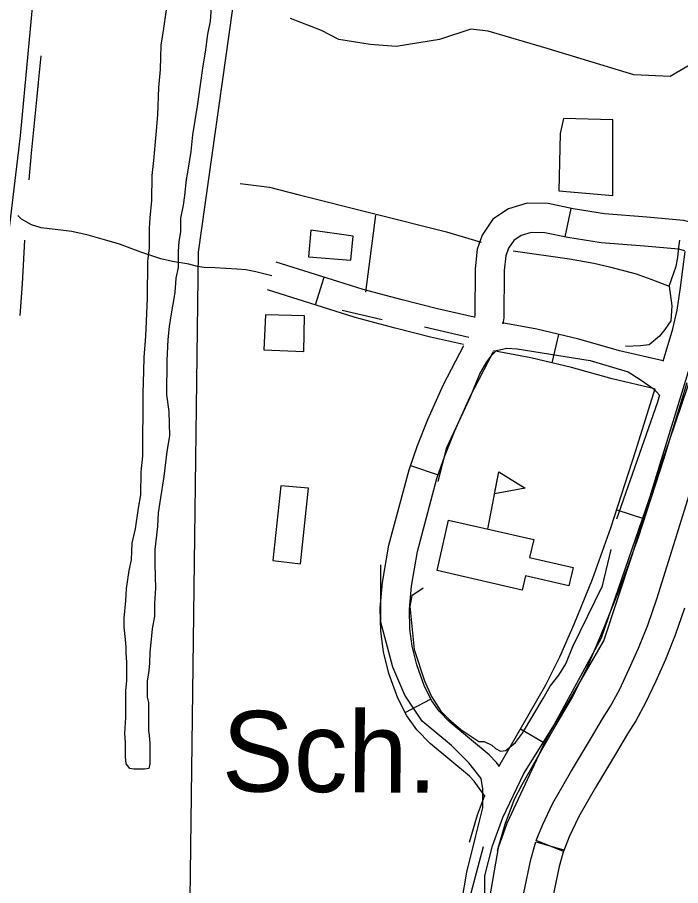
# Model space of a CAD drawing. Extents: x 3172297 to 3210190, y 958463 to 983887.
# Drawn here: x 3187024 to 3187707, y 978578 to 979472 of the extents above; entities that cross this region are included whole.
import ezdxf

# ---------------------------------------------------------------- set-up
doc = ezdxf.new("R2010")
doc.units = 0
for name, color, linetype in [('V-BLDG-IDEN', 7, 'Continuous'), ('V-BLDG-OTLN', 7, 'Continuous'), ('V-LEVE-TOET', 7, 'Continuous'), ('V-ROAD-CNTR', 7, 'Continuous'), ('V-SITE-VEGE', 7, 'Continuous'), ('V-TOPO-SHOR', 7, 'Continuous'), ('V-UTIL-LINE', 7, 'Continuous')]:
    doc.layers.add(name, color=color, linetype=linetype)

msp = doc.modelspace()

# ---------------------------------------------------------------- linework, layer by layer
at = {"layer": 'V-BLDG-OTLN'}
msp.add_line((3187508.514340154, 978944.6913213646), (3187519.741340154, 979003.6313213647), dxfattribs=at)
for points in [[(3187582.968542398, 979351.9644093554), (3187581.7884385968, 979292.9592192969), (3187637.253317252, 979288.2388040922), (3187637.253317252, 979366.1256549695), (3187586.5088538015, 979367.3057587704)], [(3187326.2959656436, 979252.2456381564), (3187323.935758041, 979225.1032507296), (3187367.5995986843, 979221.562939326), (3187369.9598062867, 979246.3451191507)], [(3187279.5343525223, 979165.3604957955), (3187278.059222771, 979129.3673298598), (3187319.067829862, 979127.5971741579), (3187319.9529077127, 979164.1803919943)], [(3187519.741340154, 979003.6313213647), (3187547.0503401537, 978986.6713213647), (3187515.418340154, 978980.9373213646)], [(3187295.6132668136, 978989.0824904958), (3187287.352540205, 978912.3757434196), (3187315.6750314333, 978908.8354320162), (3187323.935758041, 978986.7222828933)], [(3187468.154000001, 978953.8619999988), (3187555.811000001, 978933.8629999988), (3187551.610000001, 978915.4489999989), (3187596.418000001, 978905.2259999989), (3187592.113000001, 978886.3559999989), (3187547.227000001, 978896.5959999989), (3187543.879000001, 978881.9179999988), (3187456.300000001, 978901.8939999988)]]:
    msp.add_lwpolyline(points, close=True, dxfattribs=at)
at = {"layer": 'V-LEVE-TOET'}
msp.add_lwpolyline([(3187505.89, 978537.949), (3187505.563, 978587.59), (3187513.281, 978618.4060000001), (3187524.04, 978647.844), (3187545.619, 978692.898), (3187591.032, 978765.373), (3187628.0640000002, 978829.698), (3187657.186, 978917.922), (3187721.622, 979128.143)], dxfattribs=at)
at = {"layer": 'V-ROAD-CNTR'}
for p, q in [((3187588.0486666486, 979245.4247996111), (3187594.227313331, 979274.781644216)), ((3187331.165577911, 979175.3671415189), (3187340.2089301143, 979203.9716478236)), ((3187574.8979231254, 979115.8377878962), (3187581.820606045, 979145.028136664)), ((3187429.0710944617, 979010.2216276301), (3187457.398413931, 979000.3442306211)), ((3187641.2831362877, 978964.3095301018), (3187669.829274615, 978955.0835891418)), ((3187423.445433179, 978755.9751498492), (3187450.094710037, 978769.7525241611)), ((3187542.022944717, 978738.9541968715), (3187568.0250511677, 978723.9912272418))]:
    msp.add_line(p, q, dxfattribs=at)
for points in [[(3187048.2272379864, 979431.8138659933), (3187044.309334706, 979390.7621408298)], [(3187045.5481547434, 979403.742514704), (3187038.605801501, 979331.5318478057), (3187036.1556204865, 979304.1892211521)], [(3187715.649442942, 979260.9178099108), (3187709.9216832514, 979262.36518663), (3187672.2151692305, 979265.9264897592), (3187628.581476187, 979269.1162086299), (3187596.387500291, 979274.3269961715), (3187570.52576696, 979279.7700373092), (3187549.1461948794, 979280.2356563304), (3187529.86811972, 979274.3719679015), (3187513.674759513, 979263.5723010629), (3187502.814662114, 979247.337353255), (3187497.595053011, 979232.7082982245), (3187495.5340465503, 979212.5232305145), (3187495.2218352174, 979165.2778751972), (3187494.66566424, 979162.5037352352)], [(3187286.228, 979205.306), (3187269.782, 979209.582), (3187259.264, 979211.64), (3187250.169, 979212.291), (3187227.375, 979213.561), (3187216.5100000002, 979214.083), (3187209.774, 979215.103), (3187200.669, 979217.289), (3187183.8850000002, 979220.25), (3187171.9450000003, 979223.0090000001), (3187151.361, 979229.605), (3187129.23, 979237.846), (3187116.219, 979241.779), (3187097.058, 979247.323), (3187080.271, 979251.111), (3187048.8710000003, 979254.912), (3187038.815, 979257.919), (3187028.508, 979263.637), (3187024.8713716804, 979267.3825869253)], [(3187711.4425745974, 979231.0378636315), (3187704.8063167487, 979232.71481337), (3187669.7108307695, 979236.0295102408), (3187625.0845238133, 979239.2917913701), (3187590.8984997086, 979244.8250038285), (3187567.0802330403, 979249.8379626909), (3187553.2878051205, 979250.1383436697), (3187542.8318802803, 979246.9580320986), (3187535.2892404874, 979241.9276989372), (3187529.8193378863, 979233.750646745), (3187527.070946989, 979226.0477017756), (3187525.52395345, 979210.8967694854), (3187525.2021647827, 979162.2021248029), (3187523.9851124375, 979156.1315571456)], [(3187031.6632658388, 979241.9662575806), (3187029.2173945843, 979197.2261635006), (3187026.6885373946, 979164.5274314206)], [(3187689.132357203, 979117.5953481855), (3187698.9637646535, 979150.8205543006), (3187703.6057943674, 979170.1912449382), (3187706.8920058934, 979193.38427755), (3187711.6881049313, 979230.3480557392)], [(3187494.581906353, 979162.8372869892), (3187456.604749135, 979171.5495847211), (3187420.535867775, 979180.7263095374), (3187380.212822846, 979191.3011747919), (3187354.0384344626, 979199.5994326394), (3187290.7496753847, 979219.6082533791)], [(3187483.545753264, 979134.5897739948), (3187449.551250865, 979142.388415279), (3187413.032132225, 979151.6796904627), (3187371.8691771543, 979162.4748252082), (3187344.9835655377, 979170.9985673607), (3187281.7063246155, 979191.003746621)], [(3187689.1730351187, 979117.8010878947), (3187644.207267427, 979128.3184351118), (3187602.296567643, 979140.1721278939), (3187559.083073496, 979150.4204918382), (3187523.485912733, 979156.8806349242)], [(3187505.9504005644, 978669.3924843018), (3187494.3824032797, 978685.0995811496), (3187489.5336155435, 978690.1223627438), (3187449.0906654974, 978723.8788170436), (3187435.3618710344, 978738.0852313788), (3187425.2992005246, 978752.3894478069), (3187415.824975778, 978770.7152356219), (3187406.806918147, 978796.1216936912), (3187401.2819581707, 978818.2547197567), (3187398.258113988, 978839.5767814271), (3187397.7860149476, 978863.2217052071), (3187400.271350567, 978889.785445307), (3187406.7544363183, 978928.04319572), (3187427.4458907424, 979005.5607169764), (3187436.1603434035, 979030.552836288), (3187446.8752577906, 979057.5343441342), (3187462.9317218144, 979093.5245172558), (3187483.7836879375, 979133.7128668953)], [(3187520.28300559, 978700.5208497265), (3187517.3535967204, 978704.4984188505), (3187509.9963844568, 978712.1196372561), (3187469.547334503, 978745.8811829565), (3187458.5561289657, 978757.2547686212), (3187451.010799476, 978767.9805521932), (3187443.4130242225, 978782.6767643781), (3187435.563081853, 978804.7923063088), (3187430.7660418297, 978824.0092802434), (3187428.215886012, 978841.9912185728), (3187427.8139850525, 978862.1202947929), (3187430.0366494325, 978885.876554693), (3187436.0995636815, 978921.65480428), (3187456.1421092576, 978996.7412830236), (3187464.2776565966, 979020.073163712), (3187474.5267422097, 979045.8816558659), (3187489.968278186, 979080.4934827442), (3187514.4072915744, 979127.595209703)], [(3187680.215870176, 979089.0864509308), (3187636.704732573, 979099.2635648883), (3187594.749432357, 979111.1298721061), (3187552.938926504, 979121.0455081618), (3187514.3678498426, 979128.0453550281)], [(3187518.3680177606, 978613.7416318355), (3187526.4887806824, 978641.009604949), (3187535.885474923, 978666.6561358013), (3187543.768977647, 978681.8399015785), (3187575.6341894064, 978737.2141119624), (3187594.5580746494, 978769.919840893), (3187610.007775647, 978800.3921095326), (3187624.97358606, 978835.220837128), (3187644.2109237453, 978882.4796389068), (3187663.7333959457, 978936.2222289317), (3187689.6704516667, 979016.4745071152), (3187713.9221614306, 979095.6421023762)], [(3187519.8261649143, 978700.3814372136), (3187549.6498105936, 978752.2078880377), (3187568.1759253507, 978784.2261591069), (3187582.820224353, 978813.1098904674), (3187597.29641394, 978846.7991628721), (3187616.209076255, 978893.2603610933), (3187635.3526040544, 978945.9597710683), (3187661.0535483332, 979025.4814928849), (3187680.655575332, 979089.4706035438)], [(3187711.006384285, 978863.2704616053), (3187701.2809149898, 978835.4203467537), (3187691.33240909, 978810.3231891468), (3187681.41010689, 978788.2167485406), (3187670.808130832, 978765.6971480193), (3187660.80950818, 978747.3592220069), (3187652.4440869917, 978733.7540893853), (3187641.172948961, 978714.7984920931), (3187619.5280336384, 978678.718977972), (3187602.2314273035, 978648.6971931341), (3187592.3291294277, 978627.8160320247), (3187586.3319659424, 978612.8556901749), (3187558.4860340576, 978624.0183098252), (3187564.8268705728, 978639.8359679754), (3187575.6385726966, 978662.634806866), (3187593.6659663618, 978693.925022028), (3187615.4170510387, 978730.1815079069), (3187626.7719130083, 978749.2779106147), (3187634.8444918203, 978762.4067779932), (3187644.0438691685, 978779.2788519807), (3187654.1518931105, 978800.7492514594), (3187663.68959091, 978821.9988108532), (3187673.1630850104, 978845.8976532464), (3187682.517615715, 978872.6855383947), (3187701.782294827, 978934.4378940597), (3187737.5169503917, 979049.2252090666)], [(3187489.6159822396, 978622.3043681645), (3187498.0012193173, 978650.460395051), (3187505.0648461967, 978669.7392520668)], [(3187545.587983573, 978570.1138332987), (3187552.793886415, 978604.4055087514), (3187557.9873754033, 978622.5621356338), (3187586.8306245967, 978614.3118643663), (3187581.932113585, 978597.1864912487), (3187575.380016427, 978566.0061667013)], [(3187555.3000000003, 978083.843), (3187542.461, 978124.291), (3187538.0500000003, 978142.23), (3187530.483, 978180.337), (3187523.896, 978214.319), (3187518.606, 978244.9720000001), (3187511.526, 978305.343), (3187500.203, 978406.549), (3187491.577, 978484.559), (3187488.642, 978519.519), (3187488.818, 978540.666), (3187491.327, 978570.098), (3187503.992, 978618.023)]]:
    msp.add_lwpolyline(points, dxfattribs=at)
at = {"layer": 'V-SITE-VEGE'}
for p, q in [((3187174.878, 979460.081), (3187178.958, 979486.601)), ((3187224.235, 979486.302), (3187222.554, 979467.5750000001)), ((3187222.554, 979467.5750000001), (3187220.123, 979454.318)), ((3187172.423, 979442.9230000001), (3187174.878, 979460.081)), ((3187220.123, 979454.318), (3187217.657, 979435.5969999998)), ((3187171.4760000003, 979417.9450000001), (3187172.423, 979442.9230000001)), ((3187217.657, 979435.5969999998), (3187215.222, 979421.5580000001)), ((3187215.222, 979421.5580000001), (3187209.483, 979380.219)), ((3187169.791, 979399.219), (3187171.4760000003, 979417.9450000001)), ((3187168.824, 979371.118), (3187169.791, 979399.219)), ((3187209.483, 979380.219), (3187204.603, 979350.583)), ((3187167.129, 979350.8300000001), (3187168.824, 979371.118)), ((3187164.612, 979324.305), (3187167.129, 979350.8300000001)), ((3187204.603, 979350.583), (3187202.928, 979333.416)), ((3187202.928, 979333.416), (3187198.8680000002, 979310.022)), ((3187162.947, 979308.699), (3187164.612, 979324.305)), ((3187162.774, 979282.935), (3187162.947, 979308.699)), ((3187198.051, 979304.5639999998), (3187196.382, 979288.1780000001)), ((3187198.8680000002, 979310.022), (3187198.051, 979304.5639999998)), ((3187196.382, 979288.1780000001), (3187194.754, 979278.0380000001)), ((3187161.095, 979264.9890000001), (3187162.774, 979282.935)), ((3187194.754, 979278.0380000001), (3187192.323, 979264.7839999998)), ((3187160.2430000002, 979254.0650000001), (3187161.095, 979264.9890000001)), ((3187192.323, 979264.7839999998), (3187192.231, 979250.73)), ((3187160.108, 979233.767), (3187160.2430000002, 979254.0650000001)), ((3187192.231, 979250.73), (3187190.603, 979240.5909999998)), ((3187190.603, 979240.5909999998), (3187189.755, 979230.447)), ((3187158.4590000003, 979220.506), (3187160.108, 979233.767)), ((3187189.755, 979230.447), (3187189.646, 979214.0530000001)), ((3187158.207, 979182.2490000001), (3187158.4590000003, 979220.506)), ((3187189.646, 979214.0530000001), (3187187.232, 979203.139)), ((3187187.232, 979203.139), (3187186.353, 979188.309)), ((3187186.353, 979188.309), (3187182.29, 979164.1349999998)), ((3187157.271, 979158.8349999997), (3187158.207, 979182.2490000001)), ((3187156.387, 979143.225), (3187157.271, 979158.8349999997)), ((3187182.29, 979164.1349999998), (3187180.656, 979153.215)), ((3187180.656, 979153.215), (3187179.007, 979139.9539999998)), ((3187154.681, 979121.377), (3187156.387, 979143.225)), ((3187179.007, 979139.9539999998), (3187178.0810000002, 979118.098)), ((3187154.589, 979107.323), (3187154.681, 979121.377)), ((3187178.0810000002, 979118.098), (3187177.85, 979082.964)), ((3187153.659, 979084.689), (3187154.589, 979107.323)), ((3187153.2290000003, 979019.89), (3187153.659, 979084.689)), ((3187177.85, 979082.964), (3187180.078, 979065.775)), ((3187180.078, 979065.775), (3187180.6920000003, 979040.7880000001)), ((3187180.6920000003, 979040.7880000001), (3187178.2430000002, 979024.41)), ((3187151.56, 979003.5040000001), (3187153.2290000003, 979019.89)), ((3187178.2430000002, 979024.41), (3187174.95, 978998.667)), ((3187151.404, 978980.083), (3187151.56, 979003.5040000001)), ((3187174.95, 978998.667), (3187169.238, 978961.2270000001)), ((3187148.971, 978966.046), (3187151.404, 978980.083)), ((3187145.7060000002, 978944.9889999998), (3187148.971, 978966.046)), ((3187169.238, 978961.2270000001), (3187168.363, 978947.182)), ((3187142.487, 978930.175), (3187145.7060000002, 978944.9889999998)), ((3187168.363, 978947.182), (3187165.867, 978923.775)), ((3187141.592, 978913.005), (3187142.487, 978930.175)), ((3187165.867, 978923.775), (3187165.7630000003, 978908.161)), ((3187139.177, 978902.091), (3187141.592, 978913.005)), ((3187136.7120000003, 978883.37), (3187139.177, 978902.091)), ((3187165.7630000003, 978908.161), (3187166.383, 978883.954)), ((3187135.847, 978870.8840000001), (3187136.7120000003, 978883.37)), ((3187166.383, 978883.954), (3187165.5, 978868.3439999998)), ((3187134.168, 978852.937), (3187135.847, 978870.8840000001)), ((3187165.5, 978868.3439999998), (3187165.412, 978855.073)), ((3187165.412, 978855.073), (3187162.981, 978841.816)), ((3187134.107, 978843.5700000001), (3187134.168, 978852.937)), ((3187135.585, 978831.069), (3187134.107, 978843.5700000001)), ((3187162.981, 978841.816), (3187160.4790000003, 978817.632)), ((3187136.3140000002, 978823.2549999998), (3187135.585, 978831.069)), ((3187136.273, 978817.0089999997), (3187136.3140000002, 978823.2549999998)), ((3187136.992, 978807.6349999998), (3187136.273, 978817.0089999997)), ((3187160.4790000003, 978817.632), (3187160.407, 978806.701)), ((3187136.867, 978788.898), (3187136.992, 978807.6349999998)), ((3187160.407, 978806.701), (3187159.575, 978798.899)), ((3187159.575, 978798.899), (3187157.941, 978787.979)), ((3187136.015, 978777.974), (3187136.867, 978788.898)), ((3187157.941, 978787.979), (3187157.833, 978771.584)), ((3187135.833, 978750.65), (3187136.015, 978777.974)), ((3187157.833, 978771.584), (3187159.358, 978766.108)), ((3187159.358, 978766.108), (3187159.17, 978737.223)), ((3187134.944, 978734.262), (3187135.833, 978750.65)), ((3187135.663, 978724.888), (3187134.944, 978734.262)), ((3187159.17, 978737.223), (3187159.918, 978732.533)), ((3187159.918, 978732.533), (3187160.64, 978723.942)), ((3187135.565, 978710.0539999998), (3187135.663, 978724.888)), ((3187160.64, 978723.942), (3187160.501, 978702.862)), ((3187136.3000000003, 978703.023), (3187135.565, 978710.0539999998)), ((3187140.171, 978698.309), (3187136.3000000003, 978703.023)), ((3187160.501, 978702.862), (3187159.69, 978698.182)), ((3187144.0700000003, 978697.5059999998), (3187140.171, 978698.309)), ((3187155, 978697.4319999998), (3187144.0700000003, 978697.5059999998)), ((3187159.69, 978698.182), (3187155, 978697.4319999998))]:
    msp.add_line(p, q, dxfattribs=at)
at = {"layer": 'V-TOPO-SHOR'}
for p, q in [((3187392.772849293, 979267.9815776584), (3187382.7560670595, 979188.5505373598)), ((3187399.6478013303, 979159.9403904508), (3187358.6052874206, 979169.862253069)), ((3187488.879295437, 979141.8645186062), (3187443.3752068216, 979152.6901748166))]:
    msp.add_line(p, q, dxfattribs=at)
for points in [[(3187151.515772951, 978279.8443223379), (3186973.035125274, 978308.8540146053), (3186949.8499473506, 978319.624484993), (3186944.5243128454, 978332.1363195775), (3186937.4484844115, 978358.9366718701), (3186939.278145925, 978376.7873855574), (3186961.3091368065, 978621.3496683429), (3186974.205064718, 978782.0149212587), (3186994.574158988, 979076.5759788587), (3187027.3888648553, 979349.679978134), (3187051.2274429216, 979603.1654103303), (3187082.618654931, 980022.6858786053), (3187110.244587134, 980363.652610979), (3187122.844719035, 980404.6885025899), (3187130.0618231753, 980435.024561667), (3187131.8958995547, 980454.6607882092), (3187130.150120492, 980470.7348187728), (3187131.9709522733, 980485.0145067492), (3187135.5640523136, 980493.9332412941), (3187162.342330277, 980492.0815054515), (3187237.347114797, 980497.2526196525), (3187256.992171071, 980498.9895689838), (3187298.0501370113, 980495.3170013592)], [(3187720.3576917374, 979424.744063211), (3187696.2179492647, 979410.5195610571), (3187658.726594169, 979412.3977860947), (3187569.517174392, 979439.4012222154), (3187508.85388597, 979457.4064562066), (3187491.0031722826, 979459.2361177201), (3187458.8374516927, 979448.602508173), (3187414.181970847, 979441.5708283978), (3187387.403692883, 979443.4225642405), (3187355.2777060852, 979448.858570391), (3187337.444651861, 979457.830283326), (3187305.336324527, 979470.4083408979)], [(3187755.2370005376, 979449.6551533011), (3187742.2527753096, 979253.2796432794), (3187727.7346845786, 979158.6827808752), (3187720.47343178, 979110.4915932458), (3187695.2908274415, 979035.561861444), (3187625.1525313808, 978832.1855757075), (3187567.7556429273, 978726.9815929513), (3187528.2624465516, 978641.3741029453), (3187519.273074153, 978616.3989973), (3187506.593474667, 978543.2238742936), (3187531.043211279, 978321.758472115), (3187550.277685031, 978157.4427259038), (3187555.5989046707, 978143.1453784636), (3187564.5220540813, 978141.3377912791), (3187571.6905946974, 978152.0332089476)], [(3187253.5823141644, 979300.4651685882), (3187283.927202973, 979296.8190901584), (3187314.2610546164, 979288.7092295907), (3187465.9369351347, 979250.8381960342), (3187501.6207030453, 979240.036821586)], [(3187695.2384761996, 979194.9199872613), (3187702.4312985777, 979215.4357256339), (3187704.238885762, 979224.3588750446), (3187705.1581313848, 979235.0697447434), (3187706.0685472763, 979242.2095887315)], [(3187534.6306165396, 979231.0275822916), (3187592.6399174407, 979222.8492913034), (3187617.62606025, 979218.3237010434), (3187633.686846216, 979214.7129415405), (3187661.3446360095, 979207.5024596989), (3187676.5082506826, 979202.1083947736), (3187695.2384761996, 979194.9199872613), (3187697.8659745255, 979174.3799671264), (3187696.9356917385, 979159.2053152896), (3187690.664322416, 979150.2932030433), (3187685.290124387, 979143.1643962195), (3187674.5549729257, 979134.2633211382), (3187665.625201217, 979133.3926390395), (3187650.4461345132, 979132.5374089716)], [(3187457.2663866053, 978993.7442117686), (3187466.2800407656, 979028.5396381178), (3187490.512495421, 979080.2599102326), (3187500.392416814, 979104.3400520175), (3187507.565372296, 979116.8209825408), (3187512.939570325, 979123.9497893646), (3187517.4143896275, 979128.4025343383), (3187528.1340890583, 979131.0543144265), (3187538.8449587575, 979130.1350688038), (3187613.807802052, 979118.3438108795), (3187653.0603882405, 979106.6408502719), (3187665.539111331, 979098.5751383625), (3187679.7989324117, 979088.7194987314), (3187685.1400189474, 979082.4569591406), (3187683.336846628, 979075.3193225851), (3187641.0792910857, 978954.9009541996)], [(3187441.818013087, 978883.972697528), (3187430.1923126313, 978875.9665863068), (3187428.3803105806, 978865.2579240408), (3187432.7337210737, 978820.609065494), (3187443.3673306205, 978788.4433449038), (3187450.4696482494, 978772.3560697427), (3187460.2524425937, 978757.1549287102), (3187468.2673835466, 978749.1002539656), (3187480.7394843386, 978738.3562727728), (3187499.4564652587, 978725.8113266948), (3187504.813003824, 978725.7980820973), (3187512.8389819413, 978722.2071894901), (3187516.4011779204, 978718.6273340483), (3187521.751094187, 978715.9358201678), (3187527.1098401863, 978716.8153319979), (3187536.950027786, 978724.8258580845), (3187544.11636097, 978734.6285193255), (3187565.6308125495, 978770.2857980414), (3187572.803768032, 978782.7667285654), (3187581.7600289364, 978794.3504877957), (3187588.9307769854, 978805.9386618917), (3187596.116977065, 978823.7761309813), (3187626.6252159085, 978886.1940281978), (3187635.645492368, 978923.6677238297)], [(3187481.6404435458, 978561.1408107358), (3187487.0720348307, 978591.4812846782), (3187496.0923112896, 978628.9549803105), (3187503.305000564, 978657.505526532), (3187503.3270748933, 978666.4330908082), (3187503.3535640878, 978677.1461679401), (3187501.594540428, 978687.8636599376), (3187489.135684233, 978703.964179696), (3187471.324704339, 978721.8634569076), (3187441.03279392, 978746.9356896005), (3187423.2438883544, 978773.7625310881), (3187410.815936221, 978802.3616408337), (3187398.4321327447, 978848.8158791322), (3187398.5204300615, 978884.5261362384), (3187398.5778233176, 978907.737803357)]]:
    msp.add_lwpolyline(points, dxfattribs=at)
at = {"layer": 'V-UTIL-LINE'}
msp.add_lwpolyline([(3187635.262, 982082.2700000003), (3187381.813, 980448.0980000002), (3187210.375, 979229.6460000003), (3187191.674, 977791.7560000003), (3187172.991, 976976.0270000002), (3187150.431, 974766.1690000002), (3187135.8370000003, 973665.6670000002), (3187111.286, 971559.6250000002)], dxfattribs=at)

# ---------------------------------------------------------------- texts
at = {"layer": 'V-BLDG-IDEN'}
msp.add_text('Sch.', height=82.99983200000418, rotation=359.5937500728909, dxfattribs=at).set_placement((3187234.472528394, 978674.649748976))

doc.saveas('drawing.dxf')
